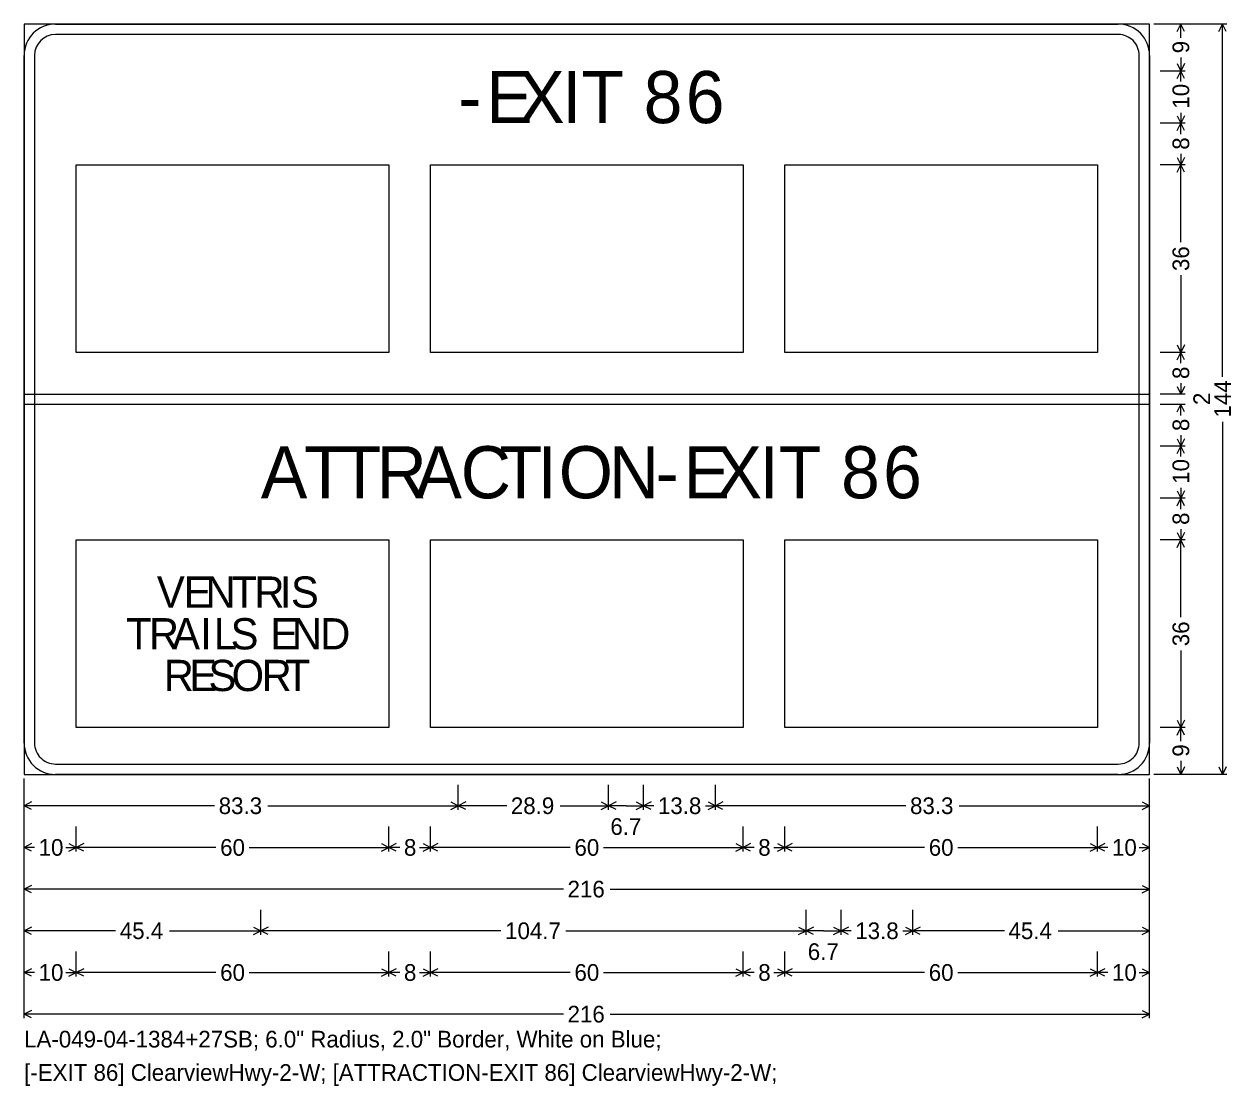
# Model space of a CAD drawing. Extents: x 667331 to 731245, y 738830 to 753817.
# Drawn here: x 718969.1 to 719316.5, y 742775.7 to 743081.4 of the extents above; entities that cross this region are included whole.
import ezdxf

# ---------------------------------------------------------------- set-up
doc = ezdxf.new("R2010")
doc.units = 0
doc.layers.add('R_SIGN', color=7, linetype='Continuous')

msp = doc.modelspace()

# ---------------------------------------------------------------- linework, layer by layer
at = {"layer": 'R_SIGN'}
for p, q in [((719315.35, 743081.36), (719294.35, 743081.36)), ((719303.35, 743081.36), (719296.15, 743081.36)), ((719301.07, 743079.21), (719302.15, 743081.36)), ((719302.15, 743077.46), (719302.15, 743081.36)), ((719303.22, 743079.21), (719302.15, 743081.36)), ((719313.07, 743079.21), (719314.15, 743081.36)), ((719314.15, 742979.8), (719314.15, 743081.36)), ((719315.22, 743079.21), (719314.15, 743081.36)), ((719302.15, 743071.77), (719302.15, 743067.86)), ((719303.35, 743067.86), (719296.15, 743067.86)), ((719301.07, 743070.01), (719302.15, 743067.86)), ((719301.07, 743065.71), (719302.15, 743067.86)), ((719303.22, 743070.01), (719302.15, 743067.86)), ((719302.15, 743064.89), (719302.15, 743067.86)), ((719303.22, 743065.71), (719302.15, 743067.86)), ((719301.07, 743055.01), (719302.15, 743052.86)), ((719302.15, 743055.83), (719302.15, 743052.86)), ((719303.22, 743055.01), (719302.15, 743052.86)), ((719303.35, 743052.86), (719296.15, 743052.86)), ((719301.07, 743050.71), (719302.15, 743052.86)), ((719302.15, 743049.72), (719302.15, 743052.86)), ((719303.22, 743050.71), (719302.15, 743052.86)), ((719302.15, 743044), (719302.15, 743040.86)), ((718984.15, 742986.86), (718984.15, 743040.86)), ((718984.15, 743040.86), (719074.15, 743040.86)), ((719074.15, 743040.86), (719074.15, 742986.86)), ((719086.15, 742986.86), (719086.15, 743040.86)), ((719086.15, 743040.86), (719176.15, 743040.86)), ((719176.15, 743040.86), (719176.15, 742986.86)), ((719188.15, 742986.86), (719188.15, 743040.86)), ((719188.15, 743040.86), (719278.15, 743040.86)), ((719278.15, 743040.86), (719278.15, 742986.86)), ((719303.35, 743040.86), (719296.15, 743040.86)), ((719301.07, 743043.01), (719302.15, 743040.86)), ((719301.07, 743038.71), (719302.15, 743040.86)), ((719303.22, 743043.01), (719302.15, 743040.86)), ((719302.15, 743018.64), (719302.15, 743040.86)), ((719303.22, 743038.71), (719302.15, 743040.86)), ((719302.15, 743009.08), (719302.15, 742986.86)), ((719301.07, 742989.01), (719302.15, 742986.86)), ((719303.22, 742989.01), (719302.15, 742986.86)), ((719074.15, 742986.86), (718984.15, 742986.86)), ((719176.15, 742986.86), (719086.15, 742986.86)), ((719278.15, 742986.86), (719188.15, 742986.86)), ((719303.35, 742986.86), (719296.15, 742986.86)), ((719301.07, 742984.71), (719302.15, 742986.86)), ((719302.15, 742983.72), (719302.15, 742986.86)), ((719303.22, 742984.71), (719302.15, 742986.86)), ((719302.15, 742978), (719302.15, 742974.86)), ((719303.35, 742974.86), (719296.15, 742974.86)), ((719301.07, 742977.01), (719302.15, 742974.86)), ((719303.22, 742977.01), (719302.15, 742974.86)), ((719303.35, 742971.86), (719296.15, 742971.86)), ((719301.07, 742969.71), (719302.15, 742971.86)), ((719302.15, 742968.72), (719302.15, 742971.86)), ((719303.22, 742969.71), (719302.15, 742971.86)), ((719314.15, 742966.92), (719314.15, 742865.36)), ((719301.07, 742962.01), (719302.15, 742959.86)), ((719302.15, 742963), (719302.15, 742959.86)), ((719303.22, 742962.01), (719302.15, 742959.86)), ((719303.35, 742959.86), (719296.15, 742959.86)), ((719301.07, 742957.71), (719302.15, 742959.86)), ((719302.15, 742956.89), (719302.15, 742959.86)), ((719303.22, 742957.71), (719302.15, 742959.86)), ((719301.07, 742947.01), (719302.15, 742944.86)), ((719302.15, 742947.83), (719302.15, 742944.86)), ((719303.22, 742947.01), (719302.15, 742944.86)), ((719303.35, 742944.86), (719296.15, 742944.86)), ((719301.07, 742942.71), (719302.15, 742944.86)), ((719302.15, 742941.72), (719302.15, 742944.86)), ((719303.22, 742942.71), (719302.15, 742944.86)), ((719302.15, 742936), (719302.15, 742932.86)), ((718984.15, 742878.86), (718984.15, 742932.86)), ((718984.15, 742932.86), (719074.15, 742932.86)), ((719074.15, 742932.86), (719074.15, 742878.86)), ((719086.15, 742878.86), (719086.15, 742932.86)), ((719086.15, 742932.86), (719176.15, 742932.86)), ((719176.15, 742932.86), (719176.15, 742878.86)), ((719188.15, 742878.86), (719188.15, 742932.86)), ((719188.15, 742932.86), (719278.15, 742932.86)), ((719278.15, 742932.86), (719278.15, 742878.86)), ((719303.35, 742932.86), (719296.15, 742932.86)), ((719301.07, 742935.01), (719302.15, 742932.86)), ((719301.07, 742930.71), (719302.15, 742932.86)), ((719303.22, 742935.01), (719302.15, 742932.86)), ((719302.15, 742910.64), (719302.15, 742932.86)), ((719303.22, 742930.71), (719302.15, 742932.86)), ((719302.15, 742901.08), (719302.15, 742878.86)), ((719301.07, 742881.01), (719302.15, 742878.86)), ((719303.22, 742881.01), (719302.15, 742878.86)), ((719074.15, 742878.86), (718984.15, 742878.86)), ((719176.15, 742878.86), (719086.15, 742878.86)), ((719278.15, 742878.86), (719188.15, 742878.86)), ((719303.35, 742878.86), (719296.15, 742878.86)), ((719303.35, 742878.86), (719296.15, 742878.86)), ((719301.07, 742876.71), (719302.15, 742878.86)), ((719302.15, 742874.96), (719302.15, 742878.86)), ((719303.22, 742876.71), (719302.15, 742878.86)), ((719301.07, 742867.51), (719302.15, 742865.36)), ((719302.15, 742869.27), (719302.15, 742865.36)), ((719303.22, 742867.51), (719302.15, 742865.36)), ((719313.07, 742867.51), (719314.15, 742865.36)), ((719315.22, 742867.51), (719314.15, 742865.36)), ((718969.15, 742795.16), (718969.15, 742864.16)), ((719293.15, 742795.16), (719293.15, 742864.16)), ((719315.35, 742865.36), (719294.35, 742865.36)), ((719303.35, 742865.36), (719296.15, 742865.36)), ((718969.15, 742855.16), (718969.15, 742862.36)), ((719094.11, 742855.16), (719094.11, 742862.36)), ((719137.42, 742855.16), (719137.42, 742862.36)), ((719147.5, 742855.16), (719147.5, 742862.36)), ((719168.18, 742855.16), (719168.18, 742862.36)), ((719168.18, 742855.16), (719168.18, 742862.36)), ((719293.15, 742855.16), (719293.15, 742862.36)), ((718971.29, 742857.44), (718969.15, 742856.36)), ((719023.96, 742856.36), (718969.15, 742856.36)), ((718971.29, 742855.29), (718969.15, 742856.36)), ((719039.3, 742856.36), (719094.11, 742856.36)), ((719091.97, 742857.44), (719094.11, 742856.36)), ((719091.97, 742855.29), (719094.11, 742856.36)), ((719096.26, 742857.44), (719094.11, 742856.36)), ((719108.07, 742856.36), (719094.11, 742856.36)), ((719096.26, 742855.29), (719094.11, 742856.36)), ((719123.46, 742856.36), (719137.42, 742856.36)), ((719135.27, 742857.44), (719137.42, 742856.36)), ((719135.27, 742855.29), (719137.42, 742856.36)), ((719139.57, 742857.44), (719137.42, 742856.36)), ((719142.46, 742856.36), (719137.42, 742856.36)), ((719139.57, 742855.29), (719137.42, 742856.36)), ((719142.46, 742856.36), (719147.5, 742856.36)), ((719145.36, 742857.44), (719147.5, 742856.36)), ((719145.36, 742855.29), (719147.5, 742856.36)), ((719149.65, 742857.44), (719147.5, 742856.36)), ((719150.41, 742856.36), (719147.5, 742856.36)), ((719149.65, 742855.29), (719147.5, 742856.36)), ((719165.28, 742856.36), (719168.18, 742856.36)), ((719166.03, 742857.44), (719168.18, 742856.36)), ((719166.03, 742855.29), (719168.18, 742856.36)), ((719170.33, 742857.44), (719168.18, 742856.36)), ((719222.99, 742856.36), (719168.18, 742856.36)), ((719170.33, 742855.29), (719168.18, 742856.36)), ((719238.34, 742856.36), (719293.15, 742856.36)), ((719291, 742857.44), (719293.15, 742856.36)), ((719291, 742855.29), (719293.15, 742856.36)), ((718969.15, 742843.16), (718969.15, 742850.36)), ((718984.15, 742843.16), (718984.15, 742850.36)), ((719074.15, 742843.16), (719074.15, 742850.36)), ((719086.15, 742843.16), (719086.15, 742850.36)), ((719176.15, 742843.16), (719176.15, 742850.36)), ((719188.15, 742843.16), (719188.15, 742850.36)), ((719278.15, 742843.16), (719278.15, 742850.36)), ((719278.15, 742843.16), (719278.15, 742850.36)), ((719293.15, 742843.16), (719293.15, 742850.36)), ((718971.29, 742845.44), (718969.15, 742844.36)), ((718982, 742845.44), (718984.15, 742844.36)), ((718986.29, 742845.44), (718984.15, 742844.36)), ((719072, 742845.44), (719074.15, 742844.36)), ((719076.29, 742845.44), (719074.15, 742844.36)), ((719084, 742845.44), (719086.15, 742844.36)), ((719088.29, 742845.44), (719086.15, 742844.36)), ((719174, 742845.44), (719176.15, 742844.36)), ((719178.29, 742845.44), (719176.15, 742844.36)), ((719186, 742845.44), (719188.15, 742844.36)), ((719190.29, 742845.44), (719188.15, 742844.36)), ((719276, 742845.44), (719278.15, 742844.36)), ((719280.29, 742845.44), (719278.15, 742844.36)), ((719291, 742845.44), (719293.15, 742844.36)), ((718972.12, 742844.36), (718969.15, 742844.36)), ((718971.29, 742843.29), (718969.15, 742844.36)), ((718981.18, 742844.36), (718984.15, 742844.36)), ((718982, 742843.29), (718984.15, 742844.36)), ((719024.38, 742844.36), (718984.15, 742844.36)), ((718986.29, 742843.29), (718984.15, 742844.36)), ((719033.92, 742844.36), (719074.15, 742844.36)), ((719072, 742843.29), (719074.15, 742844.36)), ((719077.29, 742844.36), (719074.15, 742844.36)), ((719076.29, 742843.29), (719074.15, 742844.36)), ((719083.01, 742844.36), (719086.15, 742844.36)), ((719084, 742843.29), (719086.15, 742844.36)), ((719126.38, 742844.36), (719086.15, 742844.36)), ((719088.29, 742843.29), (719086.15, 742844.36)), ((719135.92, 742844.36), (719176.15, 742844.36)), ((719174, 742843.29), (719176.15, 742844.36)), ((719179.29, 742844.36), (719176.15, 742844.36)), ((719178.29, 742843.29), (719176.15, 742844.36)), ((719185.01, 742844.36), (719188.15, 742844.36)), ((719186, 742843.29), (719188.15, 742844.36)), ((719228.38, 742844.36), (719188.15, 742844.36)), ((719190.29, 742843.29), (719188.15, 742844.36)), ((719237.92, 742844.36), (719278.15, 742844.36)), ((719276, 742843.29), (719278.15, 742844.36)), ((719281.12, 742844.36), (719278.15, 742844.36)), ((719280.29, 742843.29), (719278.15, 742844.36)), ((719290.18, 742844.36), (719293.15, 742844.36)), ((719291, 742843.29), (719293.15, 742844.36)), ((718969.15, 742831.16), (718969.15, 742838.36)), ((719293.15, 742831.16), (719293.15, 742838.36)), ((718971.29, 742833.44), (718969.15, 742832.36)), ((719124.39, 742832.36), (718969.15, 742832.36)), ((718971.29, 742831.29), (718969.15, 742832.36)), ((719137.9, 742832.36), (719293.15, 742832.36)), ((719291, 742833.44), (719293.15, 742832.36)), ((719291, 742831.29), (719293.15, 742832.36)), ((718969.15, 742819.16), (718969.15, 742826.36)), ((719037.29, 742819.16), (719037.29, 742826.36)), ((719194.24, 742819.16), (719194.24, 742826.36)), ((719204.33, 742819.16), (719204.33, 742826.36)), ((719225, 742819.16), (719225, 742826.36)), ((719225, 742819.16), (719225, 742826.36)), ((719293.15, 742819.16), (719293.15, 742826.36)), ((718971.29, 742821.44), (718969.15, 742820.36)), ((719035.14, 742821.44), (719037.29, 742820.36)), ((719039.44, 742821.44), (719037.29, 742820.36)), ((719192.09, 742821.44), (719194.24, 742820.36)), ((719196.39, 742821.44), (719194.24, 742820.36)), ((719202.18, 742821.44), (719204.33, 742820.36)), ((719206.47, 742821.44), (719204.33, 742820.36)), ((719222.86, 742821.44), (719225, 742820.36)), ((719227.15, 742821.44), (719225, 742820.36)), ((719291, 742821.44), (719293.15, 742820.36)), ((718995.49, 742820.36), (718969.15, 742820.36)), ((718971.29, 742819.29), (718969.15, 742820.36)), ((719010.95, 742820.36), (719037.29, 742820.36)), ((719035.14, 742819.29), (719037.29, 742820.36)), ((719106.42, 742820.36), (719037.29, 742820.36)), ((719039.44, 742819.29), (719037.29, 742820.36)), ((719125.11, 742820.36), (719194.24, 742820.36)), ((719192.09, 742819.29), (719194.24, 742820.36)), ((719199.28, 742820.36), (719194.24, 742820.36)), ((719196.39, 742819.29), (719194.24, 742820.36)), ((719199.28, 742820.36), (719204.33, 742820.36)), ((719202.18, 742819.29), (719204.33, 742820.36)), ((719207.23, 742820.36), (719204.33, 742820.36)), ((719206.47, 742819.29), (719204.33, 742820.36)), ((719222.1, 742820.36), (719225, 742820.36)), ((719222.86, 742819.29), (719225, 742820.36)), ((719251.34, 742820.36), (719225, 742820.36)), ((719227.15, 742819.29), (719225, 742820.36)), ((719266.81, 742820.36), (719293.15, 742820.36)), ((719291, 742819.29), (719293.15, 742820.36)), ((718969.15, 742807.16), (718969.15, 742814.36)), ((718984.15, 742807.16), (718984.15, 742814.36)), ((719074.15, 742807.16), (719074.15, 742814.36)), ((719086.15, 742807.16), (719086.15, 742814.36)), ((719176.15, 742807.16), (719176.15, 742814.36)), ((719188.15, 742807.16), (719188.15, 742814.36)), ((719278.15, 742807.16), (719278.15, 742814.36)), ((719278.15, 742807.16), (719278.15, 742814.36)), ((719293.15, 742807.16), (719293.15, 742814.36)), ((718971.29, 742809.44), (718969.15, 742808.36)), ((718972.12, 742808.36), (718969.15, 742808.36)), ((718971.29, 742807.29), (718969.15, 742808.36)), ((718981.18, 742808.36), (718984.15, 742808.36)), ((718982, 742809.44), (718984.15, 742808.36)), ((718982, 742807.29), (718984.15, 742808.36)), ((718986.29, 742809.44), (718984.15, 742808.36)), ((719024.38, 742808.36), (718984.15, 742808.36)), ((718986.29, 742807.29), (718984.15, 742808.36)), ((719033.92, 742808.36), (719074.15, 742808.36)), ((719072, 742809.44), (719074.15, 742808.36)), ((719072, 742807.29), (719074.15, 742808.36)), ((719076.29, 742809.44), (719074.15, 742808.36)), ((719077.29, 742808.36), (719074.15, 742808.36)), ((719076.29, 742807.29), (719074.15, 742808.36)), ((719083.01, 742808.36), (719086.15, 742808.36)), ((719084, 742809.44), (719086.15, 742808.36)), ((719084, 742807.29), (719086.15, 742808.36)), ((719088.29, 742809.44), (719086.15, 742808.36)), ((719126.38, 742808.36), (719086.15, 742808.36)), ((719088.29, 742807.29), (719086.15, 742808.36)), ((719135.92, 742808.36), (719176.15, 742808.36)), ((719174, 742809.44), (719176.15, 742808.36)), ((719174, 742807.29), (719176.15, 742808.36)), ((719178.29, 742809.44), (719176.15, 742808.36)), ((719179.29, 742808.36), (719176.15, 742808.36)), ((719178.29, 742807.29), (719176.15, 742808.36)), ((719185.01, 742808.36), (719188.15, 742808.36)), ((719186, 742809.44), (719188.15, 742808.36)), ((719186, 742807.29), (719188.15, 742808.36)), ((719190.29, 742809.44), (719188.15, 742808.36)), ((719228.38, 742808.36), (719188.15, 742808.36)), ((719190.29, 742807.29), (719188.15, 742808.36)), ((719237.92, 742808.36), (719278.15, 742808.36)), ((719276, 742809.44), (719278.15, 742808.36)), ((719276, 742807.29), (719278.15, 742808.36)), ((719280.29, 742809.44), (719278.15, 742808.36)), ((719281.12, 742808.36), (719278.15, 742808.36)), ((719280.29, 742807.29), (719278.15, 742808.36)), ((719290.18, 742808.36), (719293.15, 742808.36)), ((719291, 742809.44), (719293.15, 742808.36)), ((719291, 742807.29), (719293.15, 742808.36)), ((718971.29, 742797.44), (718969.15, 742796.36)), ((719291, 742797.44), (719293.15, 742796.36)), ((719124.39, 742796.36), (718969.15, 742796.36)), ((718971.29, 742795.29), (718969.15, 742796.36)), ((719137.9, 742796.36), (719293.15, 742796.36)), ((719291, 742795.29), (719293.15, 742796.36))]:
    msp.add_line(p, q, dxfattribs=at)
for points in [[(718969.15, 742865.36), (719293.15, 742865.36), (719293.15, 743081.36), (718969.15, 743081.36), (718969.15, 742865.36), (718969.15, 742865.36)], [(718978.15, 743081.36), (719284.15, 743081.36)], [(719284.15, 743078.36), (718978.15, 743078.36)], [(718969.15, 742874.36), (718969.15, 743072.36)], [(718972.15, 743072.36), (718972.15, 742874.36)], [(719290.15, 742874.36), (719290.15, 743072.36)], [(719293.15, 743072.36), (719293.15, 742874.36)], [(718969.15, 742974.86), (719293.15, 742974.86), (719293.15, 742971.86), (718969.15, 742971.86), (718969.15, 742974.86), (718969.15, 742974.86)], [(718978.15, 742868.36), (719284.15, 742868.36)], [(719284.15, 742865.36), (718978.15, 742865.36)]]:
    msp.add_lwpolyline(points, dxfattribs=at)
for centre, radius, start, end in [((718978.15, 743072.36), 9, 90.0002, 179.9998), ((718978.15, 743072.36), 6, 90.0002, 179.9998), ((719284.15, 743072.36), 9, 0, 90.0002), ((719284.15, 743072.36), 6, 0, 90.0002), ((718978.15, 742874.36), 9, 179.9998, 270.0001), ((718978.15, 742874.36), 6, 179.9998, 270.0001), ((719284.15, 742874.36), 9, 270.0001, 0.0003), ((719284.15, 742874.36), 6, 270.0001, 0.0003)]:
    msp.add_arc(centre, radius, start, end, dxfattribs=at)

# ---------------------------------------------------------------- texts
for s, p in [('9', (719304.55, 743072.97)), ('10', (719304.55, 743057.03)), ('8', (719304.55, 743045.2)), ('36', (719304.55, 743010.28)), ('8', (719304.55, 742979.2)), ('144', (719316.55, 742968.12)), ('2', (719310.55, 742971.7)), ('8', (719304.55, 742964.2)), ('10', (719304.55, 742949.03)), ('8', (719304.55, 742937.2)), ('36', (719304.55, 742902.28)), ('9', (719304.55, 742870.47))]:
    msp.add_text(s, height=4.8, rotation=90.0002, dxfattribs=at).set_placement(p)
for s, height, p in [('E', 15, (719102.16, 743052.86)), ('X', 15, (719111.4, 743052.86)), ('I', 15, (719124.03, 743052.86)), ('T', 15, (719129.54, 743052.86)), ('8', 15, (719147.5, 743052.86)), ('6', 15, (719159.62, 743052.86)), ('-', 15, (719094.11, 743052.86)), ('C', 15, (719094.83, 742944.86)), ('O', 15, (719123.06, 742944.86)), ('8', 15, (719204.33, 742944.86)), ('6', 15, (719216.44, 742944.86)), ('A', 15, (719037.29, 742944.86)), ('T', 15, (719049.75, 742944.86)), ('T', 15, (719059.67, 742944.86)), ('R', 15, (719070.6, 742944.86)), ('A', 15, (719081.78, 742944.86)), ('T', 15, (719106.02, 742944.86)), ('I', 15, (719116.95, 742944.86)), ('N', 15, (719137.46, 742944.86)), ('E', 15, (719158.99, 742944.86)), ('X', 15, (719168.22, 742944.86)), ('I', 15, (719180.85, 742944.86)), ('T', 15, (719186.36, 742944.86)), ('-', 15, (719150.94, 742944.86)), ('V', 9, (719007.36, 742913.36)), ('E', 9, (719015.09, 742913.36)), ('N', 9, (719021.34, 742913.36)), ('T', 9, (719028.87, 742913.36)), ('R', 9, (719035.43, 742913.36)), ('I', 9, (719042.75, 742913.36)), ('S', 9, (719045.95, 742913.36)), ('T', 9, (718998.49, 742901.36)), ('R', 9, (719005.05, 742901.36)), ('A', 9, (719011.76, 742901.36)), ('I', 9, (719019.84, 742901.36)), ('L', 9, (719023.76, 742901.36)), ('S', 9, (719028.59, 742901.36)), ('E', 9, (719039.98, 742901.36)), ('N', 9, (719046.23, 742901.36)), ('D', 9, (719054.37, 742901.36)), ('R', 9, (719009.34, 742889.36)), ('E', 9, (719016.66, 742889.36)), ('S', 9, (719022.21, 742889.36)), ('O', 9, (719028.87, 742889.36)), ('R', 9, (719037.51, 742889.36)), ('T', 9, (719044.22, 742889.36)), ('83.3', 4.8, (719025.16, 742853.96)), ('28.9', 4.8, (719109.27, 742853.96)), ('13.8', 4.8, (719151.61, 742853.96)), ('83.3', 4.8, (719224.19, 742853.96)), ('6.7', 4.8, (719137.92, 742847.96)), ('10', 4.8, (718973.32, 742841.96)), ('60', 4.8, (719025.58, 742841.96)), ('8', 4.8, (719078.49, 742841.96)), ('60', 4.8, (719127.58, 742841.96)), ('8', 4.8, (719180.49, 742841.96)), ('60', 4.8, (719229.58, 742841.96)), ('10', 4.8, (719282.32, 742841.96)), ('216', 4.8, (719125.59, 742829.96)), ('45.4', 4.8, (718996.69, 742817.96)), ('104.7', 4.8, (719107.62, 742817.96)), ('13.8', 4.8, (719208.43, 742817.96)), ('45.4', 4.8, (719252.54, 742817.96)), ('6.7', 4.8, (719194.75, 742811.96)), ('10', 4.8, (718973.32, 742805.96)), ('60', 4.8, (719025.58, 742805.96)), ('8', 4.8, (719078.49, 742805.96)), ('60', 4.8, (719127.58, 742805.96)), ('8', 4.8, (719180.49, 742805.96)), ('60', 4.8, (719229.58, 742805.96)), ('10', 4.8, (719282.32, 742805.96)), ('216', 4.8, (719125.59, 742793.96)), ('LA-049-04-1384+27SB; 6.0" Radius, 2.0" Border, White on Blue; ', 4.8, (718969.15, 742786.76)), ('[-EXIT 86] ClearviewHwy-2-W; [ATTRACTION-EXIT 86] ClearviewHwy-2-W; ', 4.8, (718969.15, 742777.16))]:
    msp.add_text(s, height=height, dxfattribs=at).set_placement(p)

doc.saveas('drawing.dxf')
